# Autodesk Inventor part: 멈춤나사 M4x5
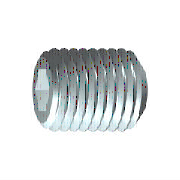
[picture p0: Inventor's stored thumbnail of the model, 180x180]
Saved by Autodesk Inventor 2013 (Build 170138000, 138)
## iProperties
IsCustomPart: 1
Created: 2012-02
Part Number: 멈춤나사 M4x5
Material: 강철, 연강
Description: 6각 소켓 머리 없는 멈춤 나사
Document SubType Name: Modeling
Standard: KS B 1028
Designer: mduedu
Standards Organization: KS
Language: ko-KR
Size Designation: 납작점M4x5
Categories: <MemberInstance><Categories><Category DisplayName="조임쇠" InternalName="e4da775c-781d-43d5-af7c-5136215cf5a6" Mnemonic="FSTN"><Category DisplayName="볼트" InternalN
Density: 7.86 g/cm^3
Mass: 0.401763 g
Surface Area: 0.994256 cm^2
Volume: 0.0511149 cm^3
Author: mduedu
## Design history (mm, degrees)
sketch "스케치1"
  geometry: L1 (0, 0)-(1.833, 0); L2 (5, 1.155)-(5, 2); L3 (5, 2)-(0, 2); L4 (5, 1.155)-(2.5, 1.155); L5 (2.5, 1.155)-(1.833, 0); L6 (0, -0.4)-(0, 2.4) reference; L7 (0, 2)-(0, 0)
  constraints: 13 end point, 3 parallel, 1 collinear, 1 perpendicular, 1 point on line
  dimensions: "d0" = 2.5 distance of L2.start L4.end (= INTI); "d1" = 60 deg angle of L5 L1; "d2" = 4 diameter of L3 L1 (= NND); "d3" = 2.3094 diameter of L4 L1 (= 1.1547 x SW); "d5" = 5 distance from line of L2 L3.end (= NLG)
revolve "본체" sketch "스케치1" stored, may be unused: angle "d6" = 90 deg
sketch "스케치2"
  geometry: L1 (-0.577, 1)-(0.577, 1); L2 (0.577, 1)-(1.155, 0); L3 (1.155, 0)-(0.577, -1); L4 (0.577, -1)-(-0.577, -1); L5 (-0.577, -1)-(-1.155, 0); L6 (-1.155, 0)-(-0.577, 1); A1 r 1.155 centre (0, 0) between (-0.577, 1) and (0.577, 1) reference; 2 further points
  constraints: 12 end point, 2 point on circle, 1 coincident, 1 horizontal, 11 other
extrude "슬롯" join sketch "스케치2" taper "d9" = 0 deg; stored distance "d21" = 10
workaxis "Work Axis1"
workplane "Work Plane1"
body "Solid1"
chamfer "모따기1" distance "d7" = 0.42941 (= -0.5 x GD1 + 0.5 x NND); stored, may be unused: angle "d8" = 45 deg (= FAWI), second distance "d29" = 0.42941 (= -0.5 x GD1 + 0.5 x NND)
feature "스레드" dims "d11" = 5 (= NLG), "d12" = 0
chamfer "모따기2" distance "d13" = 0.42941 (= -0.5 x GD1 + 0.5 x NND); stored, may be unused: angle "d14" = 45 deg (= FAWI), second distance "d30" = 0.42941 (= -0.5 x GD1 + 0.5 x NND)
other parameters: "NND" = 4 [user parameter; used in 5 equation terms], "NLG" = 5 [user parameter; used in 2 equation terms], "INTI" = 2.5 [user parameter; used in 1 equation term], "FAWI" = 45 deg [user parameter; used in 2 equation terms], "SW" = 2 [user parameter; used in 2 equation terms], "GD1" = 3.14117 (= THREADDIA - 1.2269 x PTC) [user parameter; used in 4 equation terms], "d4" = 0, "FAWI1" = 45 deg [user parameter], "d15" = 0, "d31" = 0, "GUL" = 0.42941 (= 0.61345 x PTC) [user parameter], "SPD" = 2.5 [user parameter], "TPU" = 14.28571 (computed from PTC) [user parameter], "TOA" = 30 deg [user parameter], "THREADDIA" = 4 [user parameter; used in 1 equation term], "PTC" = 0.7 [user parameter; used in 4 equation terms], "GAL" = 0.42941 (= 0.61345 x PTC) [user parameter], "E0" = 2.31 (= 1.155 x SW) [user parameter]
